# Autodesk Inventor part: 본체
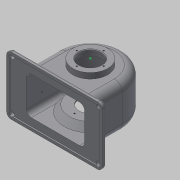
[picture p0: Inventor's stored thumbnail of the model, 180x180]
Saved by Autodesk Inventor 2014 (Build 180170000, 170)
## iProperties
Created: 2016-01
Part Number: 본체
Material: 일반
Document SubType Name: Modeling
Designer: basic
Density: 1 g/cm^3
Appearance: 기본값
Mass: 256.838 g
Surface Area: 1071.61 cm^2
Volume: 256.838 cm^3
Author: basic
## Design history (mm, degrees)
sketch "스케치7"
  geometry: L1 (-57, 0)-(-57, -57); L2 (-57, -57)-(57, -57); L3 (57, -57)-(57, 0); L4 (-57, 0)-(57, 0); 3 further points
  constraints: 8 end point, 2 coincident, 2 perpendicular, 1 horizontal alignment, 1 midpoint, 1 parallel, 1 vertical, 2 other
  dimensions: "d68" = 57 horizontal distance of L1.end point (0, 0); "d69" = 114 length of L2
extrude "돌출4" new body sketch "스케치7" stored distance "d70" = 77; taper "d71" = 0 deg
sketch "스케치8"
  geometry: C1 r 31 at (0, 0); 1 further point
  constraints: 1 centre point, 1 coincident
  dimensions: "d72" = 62 diameter of C1
extrude "돌출5" join sketch "스케치8" distance "d73" = 10; taper "d74" = 0 deg
fillet "모깎기2" dims "d75" = 14
sketch "스케치9"
  geometry: L1 (-42, 90.5)-(128, 90.5); L2 (128, 90.5)-(128, -13.5); L3 (128, -13.5)-(-42, -13.5); L4 (-42, -13.5)-(-42, 90.5); L5 (-42, 90.5)-(128, -13.5); 2 further points
  constraints: 10 end point, 2 parallel, 1 coincident, 1 horizontal, 1 midpoint, 1 perpendicular
  dimensions: "d76" = 170 distance of L2.end L3.end; "d77" = 104 distance of L1.end L2.end
extrude "돌출6" join sketch "스케치9" distance "d78" = 7; taper "d79" = 0 deg
node "작업 평면1"
sketch "스케치10"
  geometry: C1 r 6 at (0, 0); 1 further point
  constraints: 1 centre point, 1 coincident
  dimensions: "d81" = 12 diameter of C1
extrude "돌출7" join sketch "스케치10" distance "d82" = 7; taper "d83" = 0 deg
sketch "스케치14"
  geometry: L1 (43, -38.5)-(0, -38.5) reference; L2 (44.13, -38.5)-(34.899, -27.498); L3 (34.899, -27.498)-(0, -27.498); L4 (0, -38.5)-(0, -24.5) reference; L5 (0, -27.498)-(0, -11.498); L6 (0, -24.5)-(0, 24.5) reference; L7 (0, -11.498)-(28, -11.498); L8 (28, -11.498)-(49.311, -36.896); L9 (0, -27.498)-(0, -38.5); L10 (0, -38.5)-(44.13, -38.5); 1 further point
  constraints: 14 end point, 3 point on line, 2 perpendicular, 1 collinear, 1 horizontal, 1 parallel
  dimensions: "d96" = 16 distance of L3.end L5.end; "d97" = 28 distance of L5.end L7.end; "d98" = 50 deg angle of L3 L2; "d99" = 5 distance between parallel lines of L2 L8
revolve "회전4" sketch "스케치14" stored, may be unused: angle "d100" = 180 deg
sketch "스케치16"
  geometry: 1 further point
sketch "스케치18"
  geometry: L1 (8.749, -28.33)-(40.251, -28.33); L2 (40.251, -28.33)-(40.251, -39.67); L3 (40.251, -39.67)-(8.749, -39.67); L4 (8.749, -39.67)-(8.749, -28.33); L5 (76.5, -64)-(-27.5, -64) reference; L6 (40.251, -28.33)-(8.749, -39.67); L7 (8.749, -28.33)-(40.251, -39.67); L8 (-14, -9.923)-(-14, -57) reference; 4 further points
  constraints: 4 end point, 3 midpoint, 2 other
  dimensions: "d136" = 30 distance from line of L5 point (24.5, -34); "d137" = 38.5 distance from line of L8 point (24.5, -34)
feature "엠보싱1" sketch "스케치18" dims "d76" = 170, "d77" = 104, "d133" = 0.5, "d134" = 0
feature "쉘2" dims "d138" = 5
hole "구멍8" diameter "d141" = 4.459; stored, may be unused: countersink angle "d145" = 90 deg, drill point angle "d147" = 118 deg; dims "d139" = 10, "d140" = 10, "d142" = 6, "d143" = 4, "d144" = 2, "d146" = 25
sketch "스케치19"
  geometry: C1 r 20 at (0, 0); 1 further point
  constraints: 1 centre point, 1 coincident
  dimensions: "d148" = 40 diameter of C1
extrude "돌출8" cut sketch "스케치19" stored distance "d149" = 7; taper "d150" = 0 deg
sketch "스케치20"
  geometry: 2 further points
  dimensions: "d151" = 24 distance of point (0, 0) point (0, 24)
hole "구멍9" sketch "스케치20" at (0, 24) diameter "d152" = 2.459; stored, may be unused: countersink angle "d156" = 90 deg, drill point angle "d158" = 118 deg; dims "d153" = 6, "d154" = 4, "d155" = 2, "d157" = 8
sketch "스케치21"
  geometry: 2 further points
  dimensions: "d162" = 28 distance of point (0, 0) point (0, 28)
hole "구멍10" sketch "스케치21" at (0, 28) diameter "d163" = 2.459; stored, may be unused: countersink angle "d167" = 90 deg, drill point angle "d169" = 118 deg; dims "d164" = 7, "d165" = 4, "d166" = 2, "d168" = 9
fillet "모깎기3" dims "d173" = 3, "d174" = 1
fillet "모깎기4" dims "d175" = 8
hole "구멍11" diameter "d178" = 8; stored, may be unused: countersink angle "d182" = 90 deg, drill point angle "d184" = 118 deg; dims "d176" = 10, "d177" = 10, "d179" = 7, "d180" = 4, "d181" = 2, "d183" = 9
hole "구멍12" diameter "d187" = 8; stored, may be unused: countersink angle "d191" = 90 deg, drill point angle "d193" = 118 deg; dims "d185" = 10, "d186" = 10, "d188" = 7, "d189" = 4, "d190" = 2, "d192" = 9
hole "구멍13" diameter "d196" = 8; stored, may be unused: countersink angle "d200" = 90 deg, drill point angle "d202" = 118 deg; dims "d194" = 10, "d195" = 10, "d197" = 7, "d198" = 4, "d199" = 2, "d201" = 9
hole "구멍14" diameter "d205" = 8; stored, may be unused: countersink angle "d209" = 90 deg, drill point angle "d211" = 118 deg; dims "d203" = 10, "d204" = 10, "d206" = 7, "d207" = 4, "d208" = 2, "d210" = 9
fillet "모깎기5" dims "d212" = 3
fillet "모깎기6" dims "d213" = 3
chamfer "모따기1" distance "d214" = 1; stored, may be unused: second distance "d215" = 2, angle "d216" = 45 deg
node "솔리드3"
pattern_circular "원형 패턴3" dims angle "d160" = 360 deg
pattern_circular "원형 패턴4" dims angle "d171" = 360 deg
other parameters: "d80" = 63
